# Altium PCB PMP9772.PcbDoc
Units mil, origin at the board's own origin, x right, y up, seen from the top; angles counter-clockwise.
Board outline 3300 x 2400 mil, 2 copper layers (Top Layer, Bottom Layer), stack 64.8 mil thick; 65 components, 20 nets, 122 pads, 261 vias.
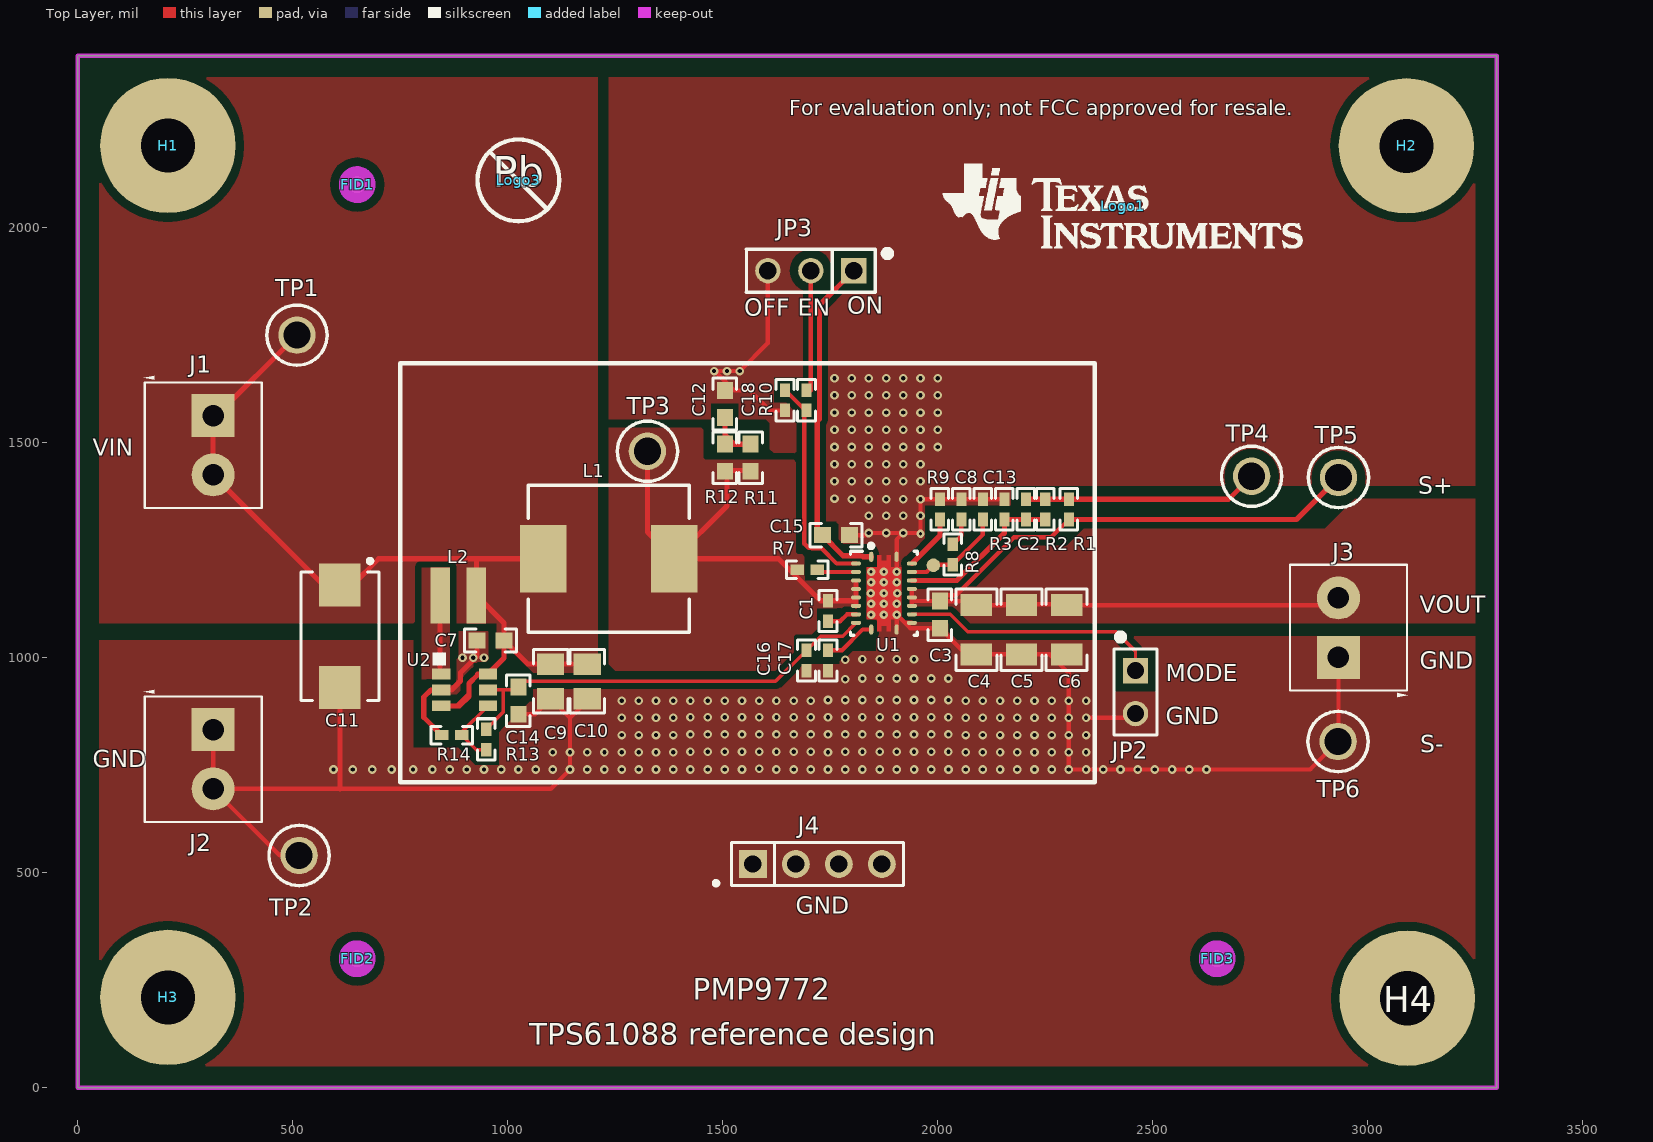
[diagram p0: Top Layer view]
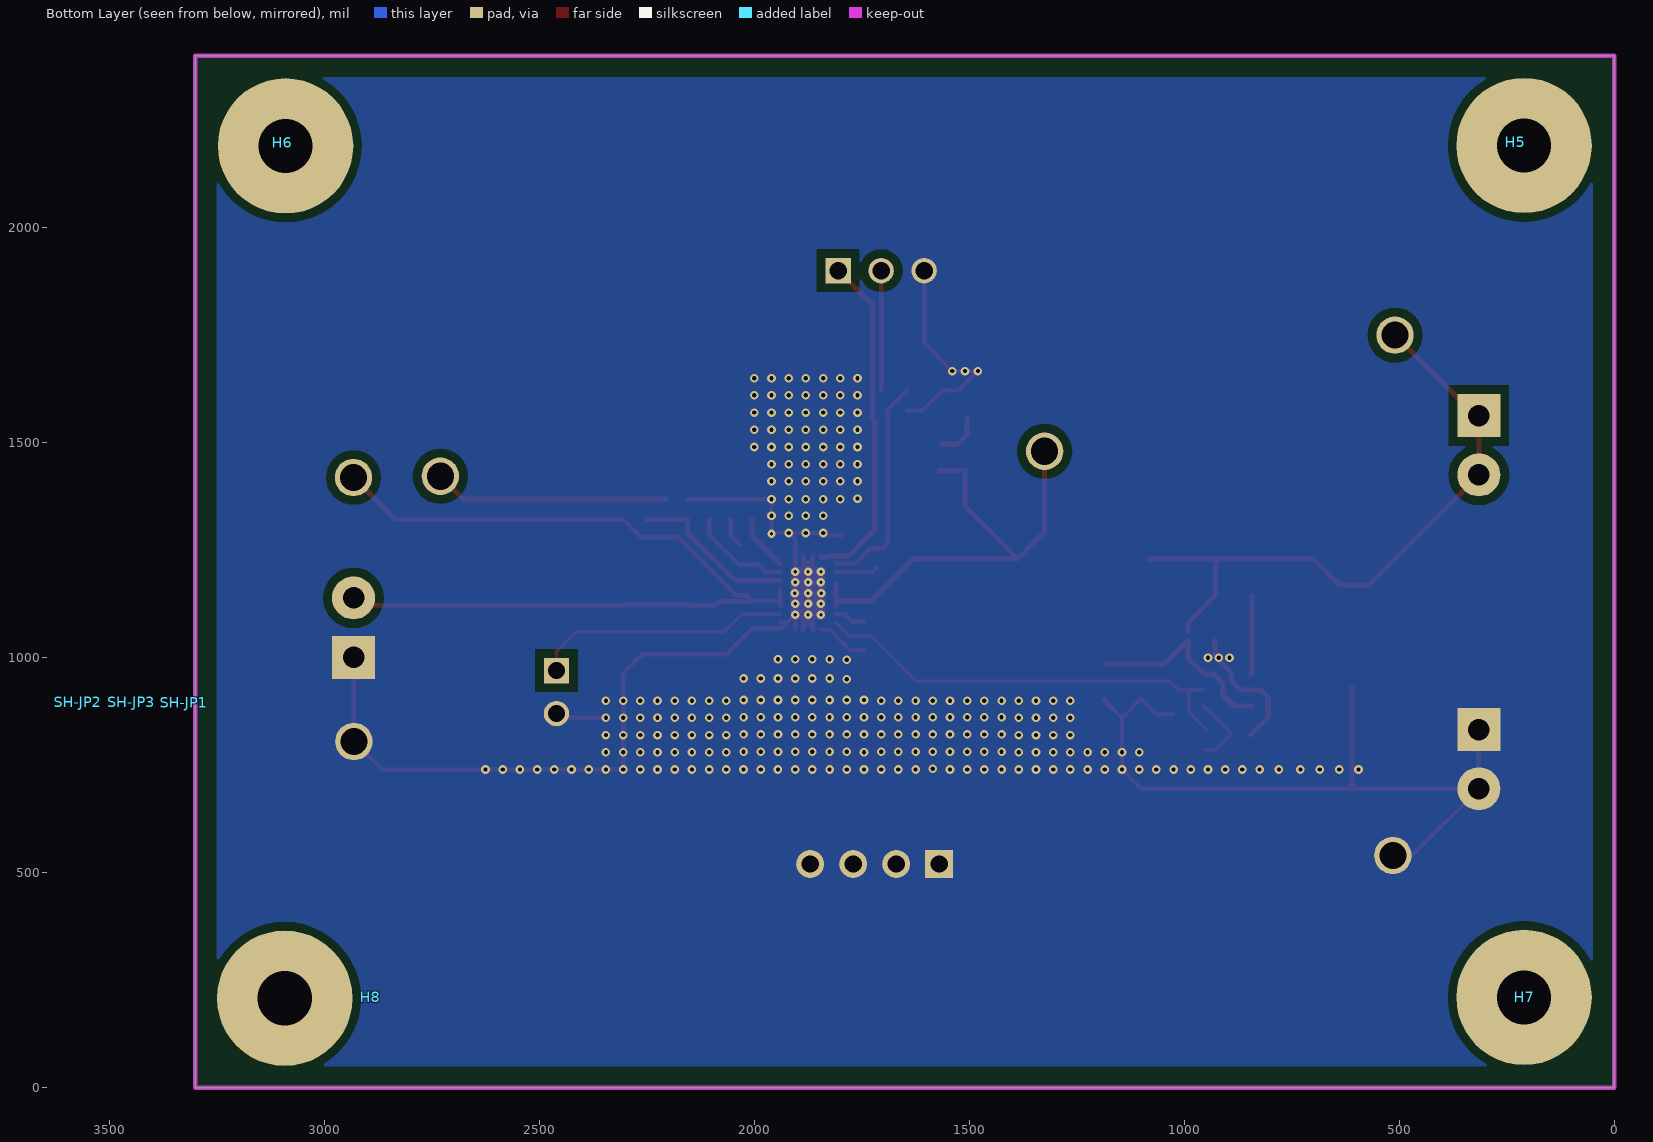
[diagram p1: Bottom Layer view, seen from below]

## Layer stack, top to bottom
Top Solder: solder mask 0.4, Solder Resist, Dk 3.5
Top Layer: signal copper 2.8
Dielectric1: core 59.2, FR-4, Dk 4.8
Bottom Layer: signal copper 2.8
Bottom Solder: solder mask 0.4, Solder Resist, Dk 3.5

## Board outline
0,0 3300,0 3300,2400 0,2400

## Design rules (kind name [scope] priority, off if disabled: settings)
AcuteAngle [All] p1: minimum=4.50000000000000E+0001 checktracksonly=FALSE
AssemblyTestPointUsage [All] p1: valid=2
Clearance Clearance_BoardEdge_MountingHoles [OnCopper and InComponentClass('Mounting Holes') vs IsKeepOut] p1: gap=40
Clearance Clearance_BoardEdge_Poly [OnCopper and InPoly vs IsKeepOut] p2: gap=20
Clearance Clearance_BoardEdge [All vs IsKeepOut] p3 off: gap=75
Clearance Clearance_Poly [InPolygon] p4: gap=20 except(14: SMDPad-Poly Fill-Poly Track-Poly; 16: Poly-Poly)
Clearance [All] p5: gap=7 except(5: THPad-Via Via-Via)
ComponentClearance ComponentClearance_Logo [InComponentClass('Logo')] p1: gap=50 collisioncheckmode=3 verticalgap=10 showdistances=FALSE
ComponentClearance ComponentClearance_ScrewToNut [(HasFootprint('NY PMS 440 0025 PH')) vs (HasFootprint('Keystone_1902C'))] p2 off: gap=0.3 collisioncheckmode=3 verticalgap=0.3 showdistances=FALSE
ComponentClearance ComponentClearance_MountingHoles [InComponentClass('Mounting Holes')] p3 off: gap=250 collisioncheckmode=3 verticalgap=100000 showdistances=FALSE
ComponentClearance ComponentClearance_SmallPassives [HasFootprint('0201*') or HasFootprint('0402*') or HasFootprint('0508') or HasFootprint('0603*') or HasFootprint('0612') or HasFootprint('0805*') or HasFootprint('0815*') or HasFootprint('0830*') or HasFootprint('1206*') or HasFootprint('1210*') or HasFootprint('1808*') or HasFootprint('1812*') or HasFootprint('1825*') or HasFootprint('2010*') or HasFootprint('2220*') or HasFootprint('2225*') or HasFootprint('2512*') or HasFootprint('2728*') or HasFootprint('3518*') vs HasFootprint('0201*') or HasFootprint('0402*') or HasFootprint('0508') or HasFootprint('0603*') or HasFootprint('0612') or HasFootprint('0805*') or HasFootprint('0815*') or HasFootprint('0830*') or HasFootprint('1206*') or HasFootprint('1210*') or HasFootprint('1808*') or HasFootprint('1812*') or HasFootprint('1825*') or HasFootprint('2010*') or HasFootprint('2220*') or HasFootprint('2225*') or HasFootprint('2512*') or HasFootprint('2728*') or HasFootprint('3518*')] p4: gap=5 collisioncheckmode=3 verticalgap=5 showdistances=FALSE
ComponentClearance ComponentClearance_THtoSMT [IsThruComponent vs IsSMTComponent] p5: gap=0 collisioncheckmode=3 verticalgap=0 showdistances=FALSE
ComponentClearance ComponentClearance_THtoTH [IsThruComponent vs IsThruComponent] p6: gap=0 collisioncheckmode=3 verticalgap=0 showdistances=FALSE
ComponentClearance [All] p7: gap=5 collisioncheckmode=3 verticalgap=5 showdistances=FALSE
DiffPairsRouting [All] p1: maxlimit=100 minlimit=10 mostfreqgap=10 toplayer_minwidth=15 toplayer_maxwidth=15 toplayer_prefwidth=15 bottomlayer_minwidth=15 bottomlayer_maxwidth=15 bottomlayer_prefwidth=15 maxuncoupledlength=1000
FabricationTestPointUsage TestPointUsage [All] p1: valid=2 allowmultiple=FALSE
FabricationTestpoint Testpoint [All] p1: side=3 testpointundercomponent=TRUE minsize=40 maxsize=100 preferedsize=60 minholesize=0 maxholesize=40 preferedholesize=32 testpointgrid=1 allowsidetop=TRUE allowsidebottom=TRUE usegrid=TRUE gridtolerance=0.01
FanoutControl Fanout_LCC [IsLCC] p1: bgadir=Out bgaviamode=Centered fanoutstyle=Auto fanoutdirection=Alternating viagrid=1 // Fanout_LCC (Default Rule)
FanoutControl Fanout_BGA [IsBGA] p2: bgadir=Out bgaviamode=Centered fanoutstyle=Auto fanoutdirection=Alternating viagrid=1 // Fanout_BGA (Default Rule)
FanoutControl Fanout_Default [All] p4: bgadir=Out bgaviamode=Centered fanoutstyle=Auto fanoutdirection=Alternating viagrid=1 // Fanout_Default (Default Rule)
FanoutControl Fanout_Small [(CompPinCount < 5)] p5: bgadir=Out bgaviamode=Centered fanoutstyle=Auto fanoutdirection=OutThenIn viagrid=1 // Fanout_Small (Default Rule)
HoleSize [All] p1: absolutevalues=TRUE maxlimit=251 minlimit=8 maxpercent=80.000 minpercent=20.000
MinimumAnnularRing MinimumAnnularRing_ThermalPadVias [IsVia and InAnyComponent] p1: minimumring=5.91
MinimumAnnularRing [All] p2: minimumring=9
MinimumSolderMaskSliver MinimumSolderMaskSliver_Logo [InComponentClass('Logo') vs InComponentClass('Logo')] p1: minsoldermaskwidth=0.7
MinimumSolderMaskSliver [All] p2: minsoldermaskwidth=3.94
PlaneConnect [All] p1: planeconnectstyle=Direct reliefexpansion=10 reliefentries=4 reliefconductorwidth=10 reliefairgap=10
PolygonConnect PolygonConnect_5 [All vs IsNamedPolygon('Top Layer-No Net')] p1: connectstyle=Direct reliefconductorwidth=10 reliefentries=4 polygonreliefangle="90 Angle" airgapwidth=10
PolygonConnect PolygonConnect_4 [All] p2: connectstyle=Direct reliefconductorwidth=10 reliefentries=4 polygonreliefangle="90 Angle" airgapwidth=10
PolygonConnect PolygonConnect_3 [All vs IsNamedPolygon('Top Layer-No Net')] p3: connectstyle=Direct reliefconductorwidth=10 reliefentries=4 polygonreliefangle="90 Angle" airgapwidth=10
PolygonConnect PolygonConnect_2 [All vs IsNamedPolygon('Bottom Layer-No Net')] p4: connectstyle=Direct reliefconductorwidth=10 reliefentries=4 polygonreliefangle="90 Angle" airgapwidth=10
PolygonConnect PolygonConnect_1 [All vs IsNamedPolygon('Bottom Layer-No Net')] p5: connectstyle=Direct reliefconductorwidth=10 reliefentries=4 polygonreliefangle="90 Angle" airgapwidth=10
PolygonConnect [IsVia + IsNamedPolygon(PGND) + InNamedPolygon(VIN)] p6: connectstyle=Relief reliefconductorwidth=10 reliefentries=4 polygonreliefangle="90 Angle" airgapwidth=10
RoutingVias ThermalPadVias [IsVia and InAnyComponent] p1: holewidth=7.87 width=19.68 viastyle="Through Hole" minholewidth=7.87 minwidth=19.68 maxholewidth=12.99 maxwidth=23.62
RoutingVias [All] p2: holewidth=16 width=34 viastyle="Through Hole" minholewidth=7.87 minwidth=26 maxholewidth=40 maxwidth=65
SMDToCorner [All] p1: distance=30000
SilkToSilkClearance [All] p1: silktosilkclearance=5
SilkToSolderMaskClearance SilkscreenOverComponentPads [IsPad] p1: minsilkscreentomaskgap=5 clearancetoexposedcopper=TRUE
SolderMaskExpansion [All] p1: expansion=1.97
UnpouredPolygon [All] p1: allowunpoured=FALSE
Width [All] p1: maxlimit=100 minlimit=6 preferedwidth=10 checkconnectedcopper=TRUE
15 further rules are at their usual default settings.

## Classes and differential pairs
component class AssemblyNote: ZZ1 ZZ2 ZZ3
component class PMP9772: C1 C2 C3 C4 C5 C6 C7 C8 C9 C10 C11 C12 C13 C14 C15 C16 C17 C18 J1 J2 J3 J4 JP2 JP3 L1 L2 R1 R2 R3 R4 R7 R8 R9 R10 R11 R12 R13 R14 TP1 TP2 TP3 TP4 TP5 TP6 U1 U2
component class Shunt: SH-JP1 SH-JP2 SH-JP3
component class Header: J4 JP2
component class "Mounting Holes": H1 H2 H3 H4
component class Logo: Logo1
component class PMP9772_Hardware: FID1 FID2 FID3 H1 H2 H3 H4 H5 H6 H7 H8 H9 Logo1 Logo2 Logo3 SH-JP1 SH-JP2 SH-JP3 ZZ1 ZZ2 ZZ3
component class FiducialMark: FID1 FID2 FID3

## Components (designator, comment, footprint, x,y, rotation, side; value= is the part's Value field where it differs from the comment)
C1 "GRM155R61C104KA88D" 0402 1745,1108.62 r270 top
C2 "C1005C0G1E102J" 0402 2205,1345 r270 top
C3 "GRM188R71E105KA12D" 0603 2005,1100 r270 top
C4 "GRM31CR61C226KE15L" 1206 2090,1065 r270 top
C5 "GRM31CR61C226KE15L" 1206 2195,1065 r270 top
C6 "GRM31CR61C226KE15L" 1206 2300,1065 r270 top
C7 "0603ZD475KAT2A" 0603 960,1040 r0 top
C8 "GRM155R71C103KA01D" 0402 2055,1345 r90 top
C9 "C2012X5R0J226M" 0805_HV 1100,945 r270 top
C10 "C2012X5R0J226M" 0805_HV 1185,945 r270 top
C11 "T495V157M010ATE150" 7343-20 610,1050 r270 top
C12 "GRM188R72A102KA01D" 0603 1505,1590 r90 top
C13 "GRM1555C1H470FA01D" 0402 2105,1345 r90 top
C14 "0603ZD475KAT2A" 0603 1025,900 r90 top
C15 "0603ZD475KAT2A" 0603 1763.5,1285 r180 top
C16 "GRM155R61C104KA88D" 0402 1695,993.62 r270 top
C17 "GRM155R71C473KA01D" 0402 1745,993.62 r90 top
C18 "GRM155R61C104KA88D" 0402 1645,1598.62 r270 top
FID1 "Fiducial" Fiducial10-20#1 650,2000 r0 top locked
FID2 "Fiducial" Fiducial10-20#2 650,300 r0 top locked
FID3 "Fiducial" Fiducial10-20#2 2650,300 r0 top locked
H1 "NY PMS 440 0025 PH" "NY PMS 440 0025 PH"#1 230,2199 r0 top
H2 "NY PMS 440 0025 PH" "NY PMS 440 0025 PH"#2 3098,2198 r0 top
H3 "NY PMS 440 0025 PH" "NY PMS 440 0025 PH"#3 210,210 r0 top locked
H4 "NY PMS 440 0025 PH" "NY PMS 440 0025 PH"#3 3092,208 r0 top
H5 "1902C" Keystone_1902C#1 230,2199 r180 bottom locked
H6 "1902C" Keystone_1902C#1 3098,2198 r180 bottom locked
H7 "1902C" Keystone_1902C#1 210,210 r180 bottom locked
H8 "1902C" Keystone_1902C#2 2893,210 r180 bottom
J1 "ED555/2DS" TERM_BLK_ED555-2DS 315,1563 r270 top
J2 "ED555/2DS" TERM_BLK_ED555-2DS 315,833 r270 top
J3 "ED555/2DS" TERM_BLK_ED555-2DS 2932,1001 r90 top
J4 "TSW-104-07-G-S" TSW-104-07-G-S 1720,520 r0 top
JP2 "PEC02SAAN" CONN_PEC02SAAN 2460,920 r270 top
JP3 "PEC03SAAN" CONN_PEC03SAAN 1705,1900 r180 top
L1 "CDMC8D28NP-R68MC" CDMC8D28 1235,1230 r0 top
L2 "LQH3NPN6R8NG0" LQH3NP_G0 885,1145 r180 top
Logo1 "Texas Instruments" TI_Stacked_Overlay_Small 2430,2050 r0 top
Logo2 "FCC disclaimer" FCC_disclaimer 3827,3801 r90 top
Logo3 "Pb-Free Symbol" Pb-Free_Overlay_Medium 1025,2110 r0 top
R1 "CRCW040249R9FKED" 0402 2305,1345 r270 top
R2 "CRCW0402205KFKED" 0402 2250,1345 r270 top
R3 "CRCW0402120KFKED" 0402 2155,1345 r270 top
R7 "CRCW0402255KFKED" 0402 1696.77,1204.61 r180 top
R8 "CRCW04024K99FKED" 0402 2035,1240 r270 top
R9 "CRCW0402100KFKED" 0402 2005,1345 r270 top
R10 "RC0402JR-070RL" 0402 1695,1598.62 r90 top
R11 "CRCW06032R05FKEA" 0603 1565,1465 r90 top
R12 "CRCW06032R05FKEA" 0603 1505,1465 r90 top
R13 "CRCW04021M00FKED" 0402 950,810 r90 top
R14 "CRCW0402162KFKED" 0402 870,820 r0 top
SH-JP1 "969102-0000-DA" SNT-100-BK-G 3327,895 r90 bottom
SH-JP2 "969102-0000-DA" SNT-100-BK-G 3573,896 r90 bottom
SH-JP3 "969102-0000-DA" SNT-100-BK-G 3449,896 r90 bottom
TP1 "5010" Keystone5010 510,1750 r0 top
TP2 "5010" Keystone5010 515,540 r0 top
TP3 "5010" Keystone5010 1325,1480 r90 top
TP4 "5010" Keystone5010 2730,1422 r90 top
TP5 "5010" Keystone5010 2932,1419 r0 top
TP6 "5010" Keystone5010 2931,805 r0 top
U1 "TPS61088RHLR" RHL0020A 1875,1150 r0 top locked (schematic designator U?)
U2 "TLV61220DBV" DBV-6 900,925 r0 top
ZZ1 "These assemblies are ESD sensitive, ESD precautions shall be observed." AssemblyNote 4050,3305 r90 top
ZZ2 "These assemblies must be clean and free from flux and all contaminants. Use of no clean flux is not acceptable." AssemblyNote 4045,2895 r90 top
ZZ3 "These assemblies must comply with workmanship standards IPC-A-610 Class 2, unless otherwise specified." AssemblyNote 4050,2475 r90 top

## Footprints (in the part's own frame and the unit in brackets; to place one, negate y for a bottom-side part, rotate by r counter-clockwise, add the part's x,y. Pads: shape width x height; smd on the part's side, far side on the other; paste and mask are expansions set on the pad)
0402 [mm] "0402 from SM-752 data"
  rect 0.8x0.6 smd: 1(-0.6,0) 2(0.6,0)
  silkscreen extent -1.22,-0.52 1.22,0.52, body extent -0.55,-0.3 0.55,0.3, height 0.6
0603 [mm] "0603 from SM-752 data"
  rect 1x0.95 smd: 1(-0.8,0) 2(0.8,0)
  silkscreen extent -1.52,-0.69 1.52,0.69, body extent -0.87,-0.47 0.87,0.47, height 0.85
0805_HV [mil] "0805 with 30mil clearance between pads"
  rect 50x63 smd: 1(-40,0) 2(40,0)
  silkscreen extent -74,-40 74,40, body extent -43,-29 43,29, height 43
1206 [mm] "1206 from SM-752 data"
  rect 1.3x1.85 smd: 1(-1.45,0) 2(1.45,0)
  silkscreen extent -2.4,-1.21 2.4,1.21, body extent -1.7,-0.9 1.7,0.9, height 1.35
7343-20 [mm] "Medium density IPC, based on Kemet case V from T495 datasheet"
  rect 2.55x2.45 smd: 1(-3.025,0) 2(3.025,0)
  silkscreen extent -4.56,-2.3 3.8,2.3, body extent -3.8,-2.3 3.8,2.3, height 2
AssemblyNote [mil] "Assembly Note"
CDMC8D28 [mm] "SMD, 2-Leads, Body 9.5x8.7mm"
  rect 2.75x4 smd: 1(-3.875,0) 2(3.875,0)
  silkscreen extent -4.75,-4.35 4.75,4.35, body extent -4.75,-4.35 4.75,4.35, height 3
CONN_PEC02SAAN [mm] "SULLINS"
  rect 1.5x1.5 hole 1.016: 1(-1.27,0)
  round 1.5 hole 1.016: 2(1.27,0)
  silkscreen extent -3.45,-1.27 2.54,1.27, body extent -2.54,-1.27 2.54,1.27, height 8.38
CONN_PEC03SAAN [mm] "SULLINS"
  rect 1.5x1.5 hole 1.016: 1(-2.54,0)
  round 1.5 hole 1.016: 2(0,0) 3(2.54,0)
  silkscreen extent -4.72,-1.27 3.81,1.27, body extent -3.84,-1.3 3.84,1.3, height 8.38
DBV-6 [mil]
  rect 42x25 smd: 1(-54.5,37) 2(-54.5,0) 3(-54.5,-37) 4(54.5,-37) 5(54.5,0) 6(54.5,37)
  silkscreen extent -75,57 -44,87
FCC_disclaimer [mil]
Fiducial10-20#1 [mm]
  round 1 smd paste-0.5 mask+0.5: 1(0,2.54)
  Top Layer keep-out circle w1.178: c0,2.54 r0.5
Fiducial10-20#2 [mm]
  round 1 smd paste-0.5 mask+0.5: 1(0,0)
  Top Layer keep-out circle w1.178: c0,0 r0.5
Keystone5010 [mil] "Keystone Multipurpose loops"
  round 87 hole 63: 1(0,0)
  silkscreen extent -70,-70 70,70, body extent -63,-63 63,62, height 319
Keystone_1902C#1 [mil] "Hex Standoff, 4-40 threaded, nylon"
  body extent -145,-126 146,126, height 501
Keystone_1902C#2 [mil] "Hex Standoff, 4-40 threaded, nylon"
  round 1 on Mech4: 0(0,0)
  body extent -145,-126 146,126, height 501
LQH3NP_G0 [mm] "MURATA"
  rect 1.15x3.3 smd: 1(-1.075,0) 2(1.075,0)
  body extent -1.6,-1.6 1.6,1.6, height 1.01
"NY PMS 440 0025 PH"#1 [mm] "4-40 nylon screw and mounting hole"
  round 8 hole 3.2: 1(-0.508,-0.203)
  body extent -3.3,-3.3 3.3,3.3, height 2.69
"NY PMS 440 0025 PH"#2 [mm] "4-40 nylon screw and mounting hole"
  round 8 hole 3.2: 1(-0.203,-0.203)
  body extent -3.3,-3.3 3.3,3.3, height 2.69
"NY PMS 440 0025 PH"#3 [mm] "4-40 nylon screw and mounting hole"
  round 8 hole 3.2: 1(0,0)
  body extent -3.3,-3.3 3.3,3.3, height 2.69
Pb-Free_Overlay_Medium [mil]
  silkscreen extent -95,-95 95,95
RHL0020A [mm] "QFN, 20-Leads, Body 4.5x3.5mm, Pitch 0.5mm, Thermal Pad 3.05x2.05mm, TI Recommended"
  oval 0.24x0.6 smd: 1(-0.75,2.15) 10(-0.75,-2.15) 11(0.75,-2.15) 20(0.75,2.15)
  oval 0.6x0.24 smd: 2(-1.65,1.75) 3(-1.65,1.25) 4(-1.65,0.75) 5(-1.65,0.25) 6(-1.65,-0.25) 7(-1.65,-0.75) 8(-1.65,-1.25) 9(-1.65,-1.75) 12(1.65,-1.75) 13(1.65,-1.25) 14(1.65,-0.75) 15(1.65,-0.25) 16(1.65,0.25) 17(1.65,0.75) 18(1.65,1.25) 19(1.65,1.75)
  rect 0.3x0.3 smd paste-0.15 mask+0: 21(0,0)
  Top Layer region: 0.16,2.25 0.16,1.925 -0.16,1.925 -0.16,2.25 -0.39,2.25 -0.39,1.525 -1.025,1.525 -1.025,-1.525 -0.39,-1.525 -0.39,-2.25 -0.16,-2.25 -0.16,-1.925 0.16,-1.925 0.16,-2.25 0.39,-2.25 0.39,-1.525 1.025,-1.525 1.025,1.525 0.39,1.525 0.39,2.25
  silkscreen extent -1.98,-2.47 1.98,2.47, body extent -1.82,-2.33 1.83,2.32, height 1.01
SNT-100-BK-G [mil] "Samtec STEP model"
  round 1 on Mech4: 0(0,0)
  body extent -100,-50 100,50, height 344
TERM_BLK_ED555-2DS [mil]
  rect 100x100 hole 50: 1(0,0)
  round 100 hole 50: 2(138,0)
  silkscreen extent -93,-161 215,113, body extent -69,-150 207,106, height 323
TI_Stacked_Overlay_Small [mil]
  silkscreen extent -418,-98 418,98
TSW-104-07-G-S [mm] "Samtec 100mil, 1x4, 230 mil above insulator"
  rect 1.65x1.65 hole 1.016 mask+0: 1(-3.81,0)
  round 1.65 hole 1.016 mask+0: 2(-1.27,0) 3(1.27,0) 4(3.81,0)
  silkscreen extent -6.1,-1.27 5.08,1.27, body extent -5.08,-1.27 5.08,1.27, height 8.38

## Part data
C1 C16 C18: "CAP, CERM, 0.1uF, 16V, +/-10%, X5R, 0402"
C2: "CAP, CERM, 1000pF, 25V, +/-5%, C0G/NP0, 0402"
C3: "CAP, CERM, 1 μF, 25 V, +/- 10%, X7R, 0603"
C4 C5 C6: "CAP, CERM, 22 μF, 16 V, +/- 10%, X5R, 1206"
C7 C14 C15: "CAP, CERM, 4.7uF, 10V, +/-10%, X5R, 0603"
C8: "CAP, CERM, 0.01 μF, 16 V, +/- 10%, X7R, 0402"
C9 C10: "CAP, CERM, 22 μF, 6.3 V, +/- 20%, X5R, 0805"
C11: "CAP, TA, 150 μF, 10 V, +/- 20%, 0.15 ohm, SMD"
C12: "CAP, CERM, 1000 pF, 100 V, +/- 10%, X7R, 0603"
C13: "CAP, CERM, 47 pF, 50 V, +/- 1%, C0G, 0402"
C17: "CAP, CERM, 0.047 μF, 16 V, +/- 10%, X7R, 0402"
FID1 FID2 FID3: "Fiducial mark.  There is nothing to buy or mount."
H1 H2 H3 H4: "Machine Screw, Round, #4-40 x 1/4, Nylon, Philips panhead"
H5 H6 H7 H8: "Standoff, Hex, 0.5\"L #4-40 Nylon"
J1 J2 J3: "Terminal Block, 6A, 3.5mm Pitch, 2-Pos, TH"
J4: "Header, 100mil, 4x1, Gold, TH"
JP2: "Header, 100mil, 2x1, Tin, TH"
JP3: "Header, 100mil, 3x1, Tin plated, TH"
L1: "Inductor, Shielded Drum Core, Metal Composite, 680 nH, 15.4 A, 0.00384 ohm, SMD"
L2: "Inductor, Wirewound, Ferrite, 6.8 μH, 0.65 A, 0.45 ohm, SMD"
Logo1: library part TI_Logo, "Texas Instrument Corporate Signature"
Logo2: library part FCC_disclaimer, "FCC_disclaimer"
Logo3: library part Pb-Free
R1: "RES, 49.9 ohm, 1%, 0.063W, 0402"
R2: "RES, 205 k, 1%, 0.063 W, 0402"
R3: "RES, 120 k, 1%, 0.063 W, 0402"
R7: "RES, 255 k, 1%, 0.063 W, 0402"
R8: "RES, 4.99 k, 1%, 0.063 W, 0402"
R9: "RES, 100k ohm, 1%, 0.063W, 0402"
R10: "RES, 0 ohm, 5%, 0.063W, 0402"
R11 R12: "RES, 2.05, 1%, 0.1 W, 0603"
R13: "RES, 1.00 M, 1%, 0.063 W, 0402"
R14: "RES, 162 k, 1%, 0.063 W, 0402"
SH-JP1 SH-JP2 SH-JP3: "Shunt, 100mil, Gold plated, Black"
TP1 TP2 TP3 TP4 TP5 TP6: "Test Point, TH, Multipurpose, Red"
U1: "13.2-V Output, Synchronous Boost Converter with 10-A Switch, RHL0020A"
U2: "IC, High Efficient, Tiny 1Cell LiIon or 1-3 Cells Alk/Nixx Boost Converter"
ZZ1 ZZ2 ZZ3: library part AssemblyNote

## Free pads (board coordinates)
  round 31.5 smd: 0(1990,1215)

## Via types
v1: diameter 20, hole 10, Top Layer to Bottom Layer, tented both sides, 229 vias
v2: diameter 20, hole 10, Top Layer to Bottom Layer, tented bottom, 16 vias
v3: diameter 19.68, hole 7.87, Top Layer to Bottom Layer, 11 vias
v4: diameter 19.68, hole 7.87, Top Layer to Bottom Layer, tented bottom, 4 vias
v5: diameter 19.68, hole 7.87, Top Layer to Bottom Layer, tented both sides, 1 vias

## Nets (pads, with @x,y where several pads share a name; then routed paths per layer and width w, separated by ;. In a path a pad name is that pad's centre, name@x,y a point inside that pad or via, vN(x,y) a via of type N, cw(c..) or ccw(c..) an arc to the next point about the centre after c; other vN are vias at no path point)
MODE: JP2.1 U1.13 | length 600.6
  Top Layer w8: U1.13 2029.21,1100.79 2070,1060 2350,1060 2415,1060 2460,1015 JP2.1
NetC1_2: C1.2 U1.8 | length 71.6
  Top Layer w10: C1.2 1773.41,1085 1789.2,1100.79 U1.8
NetC2_1: C2.1 R1.1 R2.1 TP4.1 | length 547.1
  Top Layer w12: C2.1 R2.1 R1.1 2676.62,1368.62 TP4.1
NetC2_2: C2.2 R2.2 R3.2 U1.17 | length 387.2
  Top Layer w12: U1.17 2044.53,1179.53 2155,1290 R3.2 C2.2 R2.2
NetC8_1: C8.1 R8.1 | length 66
  Top Layer w10: R8.1 2055,1283.62 C8.1
NetC12_1: C12.1 R11.2 R12.2 | length 157
  Top Layer w12: C12.1 1505,1519.18 ; 1543.3,1496.5 1527.69,1496.5 ; R11.2 1527.69,1496.5 ; 1505,1519.18 1505,1518.2 1526.7,1496.5 1527.69,1496.5 ; 1505,1519.18 1527.69,1496.5
NetC13_1: C13.1 pad.0 R8.2 U1.18 | length 236.1
  Top Layer w10: U1.18 1974.21,1199.21 pad.0 1991.38,1216.38 R8.2 2105,1286.38 C13.1
NetC17_2: C17.2 U1.10 | length 120.4
  Top Layer w10: C17.2 1777.24,1017.24 1825.36,1065.36 U1.10
NetC18_1: C18.1 R10.1 U1.2 | length 516.9
  Top Layer w10: C18.1 1692.24,1575 1690,1572.76 1690,1265 1700,1255 1706.65,1255 1707.35,1254.3 1729.5,1254.3 1764.91,1218.9 U1.2
NetJP3_2: JP3.2 R10.2 | length 278.5
  Top Layer w10: R10.2@1705,1621.5 JP3.2
NetL2_2: L2.2 U2.1 | length 184.2
  Top Layer w12: L2.2 842.68,964.82 U2.1
NetR7_1: R7.1 U1.3 | length 99.5
  Top Layer w10: R7.1@1715,1210 1725.79,1199.21 U1.3
NetR9_2: R9.2 U1.19 | length 129.4
  Top Layer w12: U1.19 2005,1283.94 R9.2
NetR13_1: R13.1 R14.2 U2.4 | length 163.5
  Top Layer w8: R13.1 927.24,786.38 R14.2 893.62,827.12 U2.4
PGND: C3.2 C4.2 C5.2 C6.2 C7.1 C8.2 C9.2 C10.2 C11.2 C12.2 C13.2 C14.1 C15.1 C16.2 C17.1 C18.2 J2.1 J2.2 J3.1 J4.1 J4.2 J4.3 J4.4 JP2.2 JP3.3 R3.1 R9.1 R14.1 TP2.1 TP6.1 U1.11 U1.12 U1.20 U1.21 U2.2 | length 4918.8
  Top Layer w10: J2.1 J2.2 ; TP2.1 470,540 J2.2 ; C14.1 1063.5,868.5 C9.2 1145,860 ; C10.2 1185,900 1145,860 ; v1(1480,1666.5) v1@1481.7,1666.5 ; JP3.3 1605,1731.5 v1(1540,1666.5) v1(1510,1666.5) v1@1481.7,1666.5 ; C18.2 1610,1575 1563.5,1621.5 1526.7,1621.5 v1@1481.7,1666.5 ; C15.1 1835,1285 v1(1840,1290) v1(1880,1290) v1(1920,1290) ; U1.11 1905,1065.83 v3(1905,1100) 1923.9,1081.1 ; v3(1905,1200) 1905,1234.18 U1.20 1904.53,1274.53 v1(1920,1290) ; U1.12 1923.9,1081.1 ; v5@1958.52,1290 v1(1920,1290) ; v5(1960.03,1288.49) v1(1960.03,1368.49) ; v1@1960.03,1370.03 v1(1960.03,1368.49) ; 2019.81,1368.49 2069.68,1368.49 2069.81,1368.62 C13.2 R3.1 ; 2040.19,1368.62 R9.1 2004.86,1368.49 v1(1960.03,1368.49) ; v1(2345,860) 2450,860 JP2.2 ; J3.1 2932,806 TP6.1 2866,740 v1(2625,740) v1(2585,740) v1(2545,740) v1(2505,740) v1(2465,740) v1(2425,740) v1(2385,740) v1(2345,740) v1(2305,740) v1(2305,780) v1(2305,820) 2305,963.5 2260.58,1007.91 C5.2 C4.2 2065.59,1007.91 C3.2 1936.5,1068.5 1923.9,1081.1 ; J2.2 610,695 1100,695 v1(1145,740) 1145,860
  Top Layer w12: 610,695 C11.2 ; R14.1 805,861.38 805,908.5 821.5,925 U2.2 869.5,925 890,945.5 890,965 928.5,1003.5 C7.1
  other v1: 595,740 640,740 685,740 730,740 780,740 825,740 865,740 905,740 945,740 985,740 1025,740 1065,740 1105,740 1185,740 1225,740 1305,740 1345,740 1385,740 1425,740 1465,740 1505,740 1545,740 1625,740 1665,740 1705,740 1745,740 1785,740 1825,740 1865,740 1905,740 1945,740 1985,740 2025,740 2065,740 2105,740 2145,740 2185,740 2225,740 2265,740 1584.97,741.51 1105,780 1145,780 1185,780 1225,780 1305,780 1345,780 1385,780 1745,780 2065,780 2105,780 2145,780 2185,780 2225,780 2265,780 2345,780 1424.97,781.51 1464.97,781.51 1504.97,781.51 1544.97,781.51 1584.97,781.51 1624.97,781.51 1664.97,781.51 1704.97,781.51 1784.97,781.51 1824.97,781.51 1864.97,781.51 1904.97,781.51 1944.97,781.51 1984.97,781.51 2024.97,781.51 1305,820 1345,820 1385,820 2065,820 2105,820 2145,820 2185,820 2225,820 2265,820 2345,820 1424.97,821.51 1464.97,821.51 1504.97,821.51 1544.97,821.51 1584.97,821.51 1624.97,821.51 1664.97,821.51 1704.97,821.51 1744.97,821.51 1784.97,821.51 1824.97,821.51 1864.97,821.51 1904.97,821.51 1944.97,821.51 1984.97,821.51 2024.97,821.51 1305,860 1345,860 1385,860 2065,860 2105,860 2145,860 2185,860 2225,860 2265,860 2305,860 1424.97,861.51 1464.97,861.51 1504.97,861.51 1544.97,861.51 1584.97,861.51 1624.97,861.51 1664.97,861.51 1704.97,861.51 1744.97,861.51 1784.97,861.51 1824.97,861.51 1864.97,861.51 1904.97,861.51 1944.97,861.51 1984.97,861.51 2024.97,861.51 1305,900 1345,900 1385,900 1425,900 1465,900 1505,900 1545,900 1585,900 1625,900 1665,900 1705,900 2065,900 2105,900 2145,900 2185,900 2225,900 2265,900 2305,900 2345,900 1744.97,901.51 1784.97,901.51 1824.97,901.51 1864.97,901.51 1904.97,901.51 1944.97,901.51 1984.97,901.51 2024.97,901.51 1944.97,996.51 895,1000 920,1000 945,1000 1840,1330 1880,1330 1920,1330 1960,1330 1800.03,1368.49 1840.03,1368.49 1880.03,1368.49 1920.03,1368.49 1760,1370 1760,1410 1800,1410 1840,1410 1880,1410 1920,1410 1960,1410 1760,1450 1800,1450 1840,1450 1880,1450 1920,1450 1960,1450 1760,1490 1800,1490 1840,1490 1880,1490 1920,1490 1960,1490 2000,1490 1760,1530 1800,1530 1840,1530 1880,1530 1920,1530 1960,1530 2000,1530 1760,1570 1800,1570 1840,1570 1880,1570 1920,1570 1960,1570 2000,1570 1760,1610 1800,1610 1840,1610 1880,1610 1920,1610 1960,1610 2000,1610 1760,1650 1800,1650 1840,1650 1880,1650 1920,1650 1960,1650 2000,1650
  other v2: 1265,740 1265,780 1265,820 1265,860 1265,900 1785,950 1824.97,951.51 1864.97,951.51 1904.97,951.51 1944.97,951.51 1984.97,951.51 2024.97,951.51 1785,995 1824.97,996.51 1864.97,996.51 1904.97,996.51
  other v3: 1845,1100 1845,1125 1875,1125 1905,1125 1875,1150 1845,1175 1875,1175 1905,1175 1845,1200
  other v4: 1875,1099.81 1844.48,1150 1905.51,1150 1875,1200.2
SW: C1.1 L1.2 R7.2 R11.1 R12.1 TP3.1 U1.4 U1.5 U1.6 U1.7 | length 1108.8
  Top Layer w12: TP3.1 1325,1292.56 L1.2 ; R11.1@1570,1435 1510,1435 1510,1352.44 L1.2 ; U1.7 U1.6 ; 1810.04,1171.41 U1.5 U1.6 ; L1.2 1630,1230 1655,1205 1727.76,1132.24 C1.1 1802.12,1132.24 U1.6
VCC: C15.2 JP3.1 U1.1 | length 789.5
  Top Layer w12: JP3.1 1725,1820 1725,1555 1720,1550 1720,1297.01 C15.2 1780.11,1236.9 1817.49,1236.9 1817.77,1236.62 1824.46,1236.62 1826.44,1234.65 U1.1
VIN: C7.2 C9.1 C10.1 C11.1 J1.1 J1.2 L1.1 L2.1 TP1.1 U2.3 U2.6 | length 2011
  Top Layer w12: TP1.1 323,1563 J1.1 J1.2 570.91,1169.09 C11.1 639.09,1169.09 700,1230 930,1230 ; U2.3 883,888 ; 991.5,1061.7 991.5,1080.83 L2.1 927.32,1227.32 930,1230 ; L1.1 930,1230 ; C10.1 C9.1 1046.5,985 C7.2 991.5,999 U2.6 930.5,962 930.5,960.5 910,940 910,915 ; 883,888 888,888 910,910 910,915 ; 883,888 910,915
VINS: C14.2 C16.1 R13.2 U1.9 U2.5 | length 1028.1
  Top Layer w8: R13.2 990,873.62 990,925 ; U2.5 990,925 ; U1.9 1778.93,1050 1727.76,1050 C16.1 1622.76,945 1033.5,945 1013.5,925 990,925
VO: C3.1 C4.1 C5.1 C6.1 J3.2 R1.2 TP5.1 U1.14 U1.15 U1.16 | length 2100.5
  Top Layer w10: U1.14 1939.96,1132.04 ; U1.16 U1.15 1939.96,1132.04 ; 2147.36,1124.06 2153.61,1124.06 ; R1.2 2263.62,1280 2177.36,1280 2042.36,1145 2018.5,1145 C3.1 ; J3.2 2915.09,1122.09 C6.1 2298.03,1124.06 2153.61,1124.06 ; 1939.96,1132.04 2004.45,1132.04 C3.1 ; C3.1 2080.59,1131.5 C4.1 2155.58,1122.09 2153.61,1124.06
  Top Layer w12: R1.2 2834.38,1321.38 TP5.1
pads on no net: FID1.1 FID2.1 FID3.1 H1.1 H2.1 H3.1 H4.1 H8.0 SH-JP1.0 SH-JP2.0 SH-JP3.0

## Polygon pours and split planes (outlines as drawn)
NetL2_2 on Top Layer "Top Layer-No Net" (solid, remove dead copper, pour order 2): 800,1210 865,1210 865,1080 865,950 800,950 800,1210
VIN on Top Layer "Top Layer-No Net 1" (solid, remove dead copper, pour order 4): 50,2350 600,2350 1150,2350 1210,2350 1210,1080 565,1080 50,1080
SW on Top Layer "Top Layer-No Net 2" (solid, remove dead copper, pour order 6): 1235,1535 1400,1535 1445,1535 1450,1535 1455,1530 1455,1465 1460,1460 1590,1460 1665,1460 1670,1455 1670,1245 1675,1240 1685,1240 1690,1235 1690,1190 1695,1185 1820,1185 1820,1115 1765,1115 1760,1110 1730,1110 1725,1110 1720,1105 1720,1060 1715,1055 1670,1055 1665,1050 1665,1010 1660,1005 1625,970 1500,970 1250,970 1240,980 1235,985 1235,1030
PGND on Top Layer "Top Layer-No Net 3" (solid, remove dead copper, pour order 8): 1235,1555 1350,1555 1600,1555 1610,1545 1610,1485 1620,1475 1980,1475 1990,1465 1990,1355 2170,1355 2170,1400 2500,1400 2600,1400 3250,1400 3250,1650 3250,2350 2450,2350 1235,2350
PGND on Top Layer "Top Layer-No Net 4" (solid, remove dead copper, pour order 10): 1835,1180 1835,1209.69 1834.65,1210.04 1859.65,1210.04 1859.65,1250.35 1859.65,1255.37 1855.37,1259.8 1850,1260 1847.93,1265 1770,1265 1770,1310 1765,1315 1745,1315 1740,1315 1740,1500 2010,1500 2010,1355 1970,1355 1970,1275 1965,1270 1950,1255 1945,1255 1915,1225 1915,1180
PGND on Top Layer "Top Layer-No Net 5" (solid, remove dead copper, pour order 12): 825,935 865,935 880,950 880,995 885,1000 885.98,1000.98 885.98,1060.99 954.01,1060.99 955,1060 955,1000 955,995 950,990 930,990 915,975 910,970 905,965 900,960 895,955 895,950 895,920 890,915 825,915 825,935
VIN on Top Layer "Top Layer-No Net 6" (solid, remove dead copper, pour order 14): 975,1097.32 977.32,1095 1210,1095 1210,965 1065,965 1060,965 1005,1020 1000,1020 975,1020 975,1135 1210,1135 1043.01,1085.26
VO on Top Layer "Top Layer-No Net 7" (solid, remove dead copper, pour order 17): 1930,1165 2040,1165 2090,1165 2185,1260 2300,1260 2340,1300 2850,1300 2900,1300 2970,1370 3250,1370 3250,1080 2850,1080 2075,1080 2050,1105 2045,1110 1965,1110 1960,1115 1930,1115
PGND on Top Layer "Top Layer-No Net 8" (solid, remove dead copper, pour order 19): 50,1040 350,1040 780,1040 780,790 885,790 925,750 980,750 980,826.99 989,835.99 1058.01,905 1060,905 1060,930 1320,930 1635,930 1635.88,930 1674.5,968.62 1680,974.12 1680,975 1680,985 1770,985 1780,985 1810,1015 1970,1015 2035,1015 2032.27,1017.73 2032.27,1040.02 2440.02,1040.02 2450,1050 3250,1050 3250,50 2850,50 50,50 50,1040
PGND on Top Layer "Bottom Layer-No Net" (solid, remove dead copper, pour order 21): 1835,1115 1915,1115 1915,1090.31 1915.35,1089.96 1920.31,1085 2025,1085 2025,1060 2045,1040 2045,997.64 2042.36,995 2042.36,985 1765,985 1795.49,1015.49 1857.03,1015.49 1857.03,1087.35 1854.42,1089.96 1834.65,1089.96 1834.65,1114.65 1835,1115
PGND on Bottom Layer "Bottom Layer-No Net 1" (solid, remove dead copper, pour order 23): 55,2350 3250,2350 3250,50 50,50 50,2350 55,2350

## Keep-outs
Keep-Out Layer:
  lines w10: 0,0 0,0 ; 0,0 3300,0 3300,2400 0,2400 0,0 ; 4434,3455 cw(c4434,3450) 4439,3450 ; 4434,3455 cw(c4434,3450) 4439,3450 ; 4434,3455 cw(c4434,3450) 4439,3450 ; 4434,3455 cw(c4434,3450) 4439,3450 ; 4434,3455 cw(c4434,3450) 4439,3450 ; 4434,3455 cw(c4434,3450) 4439,3450
  text ".Layer_Name" at 61,-858.49 h30

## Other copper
Top Layer:
  text ".Layer_Name" at 61,-858.49 h30
Bottom Layer:
  text ".Layer_Name" at 61,-858.49 h30

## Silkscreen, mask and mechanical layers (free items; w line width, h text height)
Top Overlay:
  circle w10: c1845,1260 r5
  lines w10: 750,710 2365,710 2365,1670 2365,1685 1250,1685 750,1685 750,710
  text "ON" at 1790,1800 h40
  text "OFF" at 1550,1795 h40
  text "EN" at 1675,1795 h40
  text "VIN" at 35,1470 h40
  text "S+" at 3117,1381 h40
  text "VOUT" at 3121,1105 h40
  text "GND" at 3121,974 h40
  text "MODE" at 2530,945 h40
  text "GND" at 2530,845 h40
  text "S-" at 3122,780 h40
  text "GND" at 35,745 h40
  text "GND" at 1670,405 h40
  text "PMP9772" at 1430,205 h50
  text "TPS61088 reference design" at 1050,100 h50
  text ".Layer_Name" at 61,-858.49 h30
Bottom Overlay:
  text ".Layer_Name" at 61,-858.49 h30
Top Paste:
  text ".Layer_Name" at 61,-858.49 h30
Bottom Paste:
  text ".Layer_Name" at 61,-858.49 h30
Top Solder:
  text ".Layer_Name" at 61,-858.49 h30
  text ".Layer_Name" at 61,-858.49 h30
Bottom Solder:
  text ".Layer_Name" at 61,-858.49 h30
Drill Guide:
  text ".Layer_Name" at 61,-858.49 h30
M1 Board Outline:
  lines w10: -5,0 ccw(c0,0) 0,-5 ; -5,0 ccw(c0,0) 0,-5 ; -5,0 -5,2400 ; -5,2400 cw(c0,2400) 0,2405 ; -5,2400 cw(c0,2400) 0,2405 ; 0,-5 3300,-5 ; 0,2405 3300,2405 ; 3300,-5 ccw(c3300,0) 3305,0 ; 3300,-5 ccw(c3300,0) 3305,0 ; 3300,2405 cw(c3300,2400) 3305,2400 ; 3300,2405 cw(c3300,2400) 3305,2400 ; 3305,0 3305,2400
  text ".Layer_Name" at 61,-858.49 h30
M2 Board Dimensions:
  rectangle: -516.5,-285.5 -391.5,-160.5
  rectangle: -391.5,-410.5 -16.5,-285.5
  lines w7: -516.5,-285.5 483.5,-285.5 ; -391.5,-410.5 -391.5,-160.5 ; -266.5,-410.5 -266.5,-160.5 ; -16.5,-410.5 -16.5,-160.5 ; 233.5,-410.5 233.5,-160.5 ; -516.5,-410.5 483.5,-410.5 483.5,-160.5 -516.5,-160.5 -516.5,-410.5
  lines w10: -516.5,-475.5 -516.5,-455.5 ; -456.5,-485.5 -516.5,-465.5 ; -456.5,-445.5 -516.5,-465.5 ; -292.42,-465.5 -516.5,-465.5 ; -97,160 -77,100 ; -97,2340 -77,2400 ; -87,100 -67,100 ; -87,2400 -67,2400 ; -77,969.09 -77,100 ; -77,1530.91 -77,2400 ; -57,160 -77,100 ; -57,2340 -77,2400 ; 1,-105 1,-85 ; 60.99,-115.02 1,-95 ; 61.01,-75.02 1,-95 ; 259.41,-465.5 483.5,-465.5 ; 423.5,-485.5 483.5,-465.5 ; 423.5,-445.5 483.5,-465.5 ; 483.5,-475.5 483.5,-455.5 ; 1370.09,-95.41 1,-95 ; 1931.91,-95.59 3301,-96 ; 3240.99,-115.98 3301,-96 ; 3241.01,-75.98 3301,-96 ; 3301,-106 3301,-86
  text "2300 (mil)" at -41.01,979.09 h60 r90
  text "3300 (mil)" at 1380.07,-131.41 h60 r359.98
  text "1000 (mil)" at -282.42,-501.49 h60
  text ".Layer_Name" at 61,-858.49 h30
M3 3D STEP Top:
  text ".Layer_Name" at 61,-858.49 h30
M4 3D STEP Bottom:
  text ".Layer_Name" at 61,-858.49 h30
M5 Assembly Top:
  lines w10: -808,-930.17 5792,-930.17 ; -808,-726.83 5794,-726.83 ; -808,-523.5 -808,-1133.5 3197,-1133.5 5794,-1133.5 5794,-523.5 -807.5,-523.5 -807.5,-1133.5 768,-1133.5 ; 1657,-1133.5 1657,-523.5 ; 2924,-726.83 2924,-523.5 ; 3764,-726.83 3764,-523.5 ; 4386,-1140 4386,-937.17
  text "COMPONENTS MARKED 'DNP' SHOULD NOT BE POPULATED." at 637.5,-318.5 h30
  text "ASSEMBLY VARIANT:" at 637,-434 h30
  text ".VariantName" at 1673,-434 h30
  text "PCB VIEWED FROM TOP SIDE" at -744.5,-655.67 h30
  text "BOARD #:" at 1732,-655.67 h30
  text ".PRJ_Number" at 2277.5,-655.67 h30
  text "REV:" at 3122,-655.67 h30
  text ".PCB_Rev" at 3413.5,-655.67 h30
  text "SVN REV:" at 3960,-655.67 h30
  text ".VersionControl_RevNumber" at 4466,-655.67 h30
  text "IGNORE ->" at -744.5,-858.49 h30
  text "PLOT NAME =" at -744.5,-1064.34 h30
  text ".plot_File_Name" at 61,-1064.34 h30
  text "GENERATED    :" at 1734,-1064.34 h30
  text ".Print_Date" at 2603.5,-1064.34 h30
  text ".Print_Time" at 3332.5,-1064.34 h30
  text "TEXAS INSTRUMENTS" at 4597,-1064.34 h30
M6 Assembly Bottom:
  lines w10: -808.5,-727.33 5793.5,-727.33 ; -806.5,-930.67 5793.5,-930.67 ; 599.5,-1140.5 599.5,-937.67 ; 1221.5,-727.33 1221.5,-524 ; 2061.5,-727.33 2061.5,-524 ; 3328.5,-1134 3328.5,-524 ; 4217.5,-1134 5793,-1134 5793,-524 -808.5,-524 -808.5,-1134 1788.5,-1134 5793.5,-1134 5793.5,-524
  text "COMPONENTS MARKED 'DNP' SHOULD NOT BE POPULATED." at 5586,-318 h30
  text ".VariantName" at 4542,-434 h30
  text "ASSEMBLY VARIANT:" at 5581,-434 h30
  text ".VersionControl_RevNumber" at 519.5,-656.17 h30
  text "SVN REV:" at 1025.5,-656.17 h30
  text ".PCB_Rev" at 1572,-656.17 h30
  text "REV:" at 1863.5,-656.17 h30
  text ".PRJ_Number" at 2708,-656.17 h30
  text "BOARD #:" at 3253.5,-656.17 h30
  text "PCB VIEWED FROM BOTTOM SIDE" at 5730,-656.17 h30
  text "IGNORE ->" at 2031.85,-858.49 h30
  text "TEXAS INSTRUMENTS" at 388.5,-1064.84 h30
  text ".Print_Time" at 1653,-1064.84 h30
  text ".Print_Date" at 2382,-1064.84 h30
  text "GENERATED    :" at 3251.5,-1064.84 h30
  text ".plot_File_Name" at 4924.5,-1064.84 h30
  text "PLOT NAME =" at 5730,-1064.84 h30
M9 Title Sheet:
  drawing of 57 lines, arcs and shapes, not listed
  text "1" at 223.84,8036.5 h30
  text "2" at 2719.5,8036.5 h30
  text "3" at 5208.84,8036.5 h30
  text "4" at 7715.51,8036.5 h30
  text "5" at 10214.5,8036.5 h30
  text "6" at 12719.5,8036.5 h30
  text "A" at -932.5,6893.5 h30
  text "A" at 13867.5,6893.5 h30
  text "B" at -932.5,4513.5 h30
  text "B" at 13867.5,4513.5 h30
  text "C" at -932.5,2138.5 h30
  text "C" at 13867.5,2138.5 h30
  text "PROJECT TITLE:" at 10827.5,277.5 h30
  text ".PRJ_Title" at 10877.5,144.17 h30
  text "DESIGNED FOR:" at 10827.5,-23.5 h30
  text ".PRJ_Customer" at 10877.5,-163.5 h30
  text "D" at -932.5,-231.5 h30
  text "D" at 13867.5,-231.5 h30
  text "FILE NAME:" at 10827.5,-323.5 h30
  text ".PCB_File_Name_No_Path" at 10877.5,-443.5 h30
  text "Texas Instruments (TI) and/or its licensors do not warrant the accuracy or completeness of this specification" at 5858,-605.34 h30
  text "ENGINEER:" at 10827.5,-613.5 h30
  text "LAYOUT BY:" at 12332.5,-613.5 h30
  text "or any information contained therein. TI and/or its licensors do not warrant that this design will meet" at 5813.01,-718 h30
  text ".PRJ_Engineer" at 10877.5,-768.49 h30
  text ".PCB_Layout" at 12383,-768.49 h30
  text "the specifications, will be suitable for your application or fit for any particular purpose, or will operate in" at 5813.01,-830.67 h30
  text ".Layer_Name" at 61,-858.49 h30
  text "ALTIUM DESIGNER VERSION:" at 12332.5,-923.5 h30
  text "an implementation. TI and/or its licensors do not warrant that the design is production worthy. You should" at 5813.01,-943.33 h30
  text "completely validate and test your design implementation to confirm the system functionality for your application." at 5858,-1056 h30
  text ".print_Scale" at 10877.5,-1056.83 h30
  text ".Application_BuildNumber" at 12383,-1056.83 h30
  text "1" at 223.84,-1263.5 h30
  text "2" at 2719.5,-1263.5 h30
  text "3" at 5208.84,-1263.5 h30
  text "4" at 7715.51,-1263.5 h30
  text "5" at 10214.5,-1263.5 h30
  text "6" at 12719.5,-1263.5 h30
M10 Fab Notes:
  drawing of 212 lines, arcs and shapes, not listed
  text "DESIGN INFORMATION" at 11865.02,6810 h30
  text "(REFER ALSO ARRAY/PANEL PROFILING INFORMATION)" at 11503.46,6648.29 h30
  text "BOARD SIZE" at 10817.46,6644 h30
  text "3450MIL" at 11279.78,6516.18 h30
  text "X" at 11785.46,6516.18 h30
  text "4950MIL" at 12016.78,6516.18 h30
  text "Number of Layers :" at 11220.46,6319 h30
  text "4" at 12315.27,6309 h30
  text "MIN. TRACK WIDTH:" at 11220.46,6180 h30
  text "8" at 12316.7,6180 h30
  text "MIL" at 12471.46,6180 h30
  text "MIN. CLEARANCE:" at 11220.46,6048 h30
  text "8" at 12316.7,6048 h30
  text "MIL" at 12471.46,6048 h30
  text "MIN. VIA PAD SIZE:" at 11220.46,5916 h30
  text "24" at 12286.71,5916 h30
  text "MIL" at 12471.46,5916 h30
  text "0.05mm (2MIL)" at 11915.46,5774.29 h30
  text "MINIMUM ANNULAR RING" at 10891.23,5770 h30
  text "EXTERNAL" at 12623.46,5770 h30
  text "PER" at 11091.23,5652 h30
  text "IPC-D-275 CLASS 2 LEVEL C" at 11311.23,5652 h30
  text "MIL, HOLES" at 12799.46,5539.71 h30
  text "+/-" at 12407,5539 h30
  text "+/-" at 13261,5539 h30
  text "REGISTRATION TOLERANCES:" at 10891.23,5534 h30
  text "METAL" at 12091,5534 h30
  text "5" at 12667.2,5534 h30
  text "3" at 13500.2,5534 h30
  text "MIL" at 13616.46,5534 h30
  text "MATERIAL:" at 10816.46,5324.54 h30
  text "FR-4 High Tg" at 11802.9,5184.21 h30
  text "FR-408" at 11237.46,5175.64 h30
  text "X" at 11649.46,5175.64 h30
  text "OTHER" at 12725.46,5175.64 h30
  text "62 MIL (1.6mm) +/-10%" at 11557.56,5012.92 h30
  text "THICKNESS:" at 10891.23,5008.64 h30
  text "X" at 11429.4,5008.64 h30
  text "OTHER" at 12842.46,5008.64 h30
  text "TOLERANCE:" at 10891.23,4850.64 h30
  text "X" at 11730.53,4850.64 h30
  text "ANSI IPC-6012 TYPE 3 CLASS 2" at 11917.47,4850.64 h30
  text "OTHER +/-" at 11917.46,4694.64 h30
  text "BOW & TWIST:" at 10891.23,4537.64 h30
  text "X" at 11730.53,4537.64 h30
  text "ANSI IPC-6012 TYPE 3 CLASS 2" at 11917.47,4537.64 h30
  text "OTHER +/-" at 11917.46,4379.13 h30
  text "COPPER THICKNESS (FINISHED):" at 10816.46,4243.64 h30
  text "1.4MIL (1oz)" at 11696.46,4090.92 h30
  text "2MIL (1.4oz)" at 12463.46,4090.92 h30
  text "2.8MIL (2oz)" at 13190.46,4090.92 h30
  text "X" at 13070,4089 h30
  text "OUTER:" at 11173.46,4086.64 h30
  text "1.4MIL (1oz)" at 11696.46,3933.92 h30
  text "2.8MIL (2oz)" at 12463.46,3933.92 h30
  text "N/A" at 13190,3934.29 h30
  text "INNER SIGNAL:" at 10884.38,3929.64 h30
  text "X" at 11569.42,3929.64 h30
  text "DRILLING:" at 10816.46,3790.64 h30
  text "REFERENCE:" at 10891.23,3673.64 h30
  text "X" at 11539.46,3673.64 h30
  text "AS SHOWN" at 11726.46,3673.64 h30
  text "X" at 12440.46,3673.64 h30
  text "NC_DRILL FILES" at 12577.46,3673.64 h30
  text "PTH MIN COPPER THICKNESS:" at 10891.23,3515.64 h30
  text "X" at 12241.46,3515.64 h30
  text "1MIL" at 12378.46,3515.64 h30
  text "OTHER" at 12875.46,3515.64 h30
  text "BOARD FINISH:" at 10816.46,3356.64 h30
  text "SILKSCREEN:" at 10971.68,3238.64 h30
  text "X" at 11920.46,3238.64 h30
  text "TOP" at 12046.46,3238.64 h30
  text "X" at 12430.46,3238.64 h30
  text "BOTTOM" at 12557.46,3238.64 h30
  text "SILKSCREEN COLOR:" at 10971.68,3071.64 h30
  text "X" at 11919.42,3071.64 h30
  text "WHITE" at 12046.46,3071.64 h30
  text "OTHER" at 12557.46,3071.64 h30
  text "SOLDER RESIST COLOR:" at 10971.68,2901.64 h30
  text "X" at 11539.42,2742.44 h30
  text "GREEN" at 11666.46,2742.44 h30
  text "BLUE" at 12257.46,2742.44 h30
  text "OTHER" at 12795.46,2742.44 h30
  text "IMMERSION GOLD (ENIG)" at 11877.46,2553.92 h30
  text "ENEPIG" at 13215,2550.64 h30
  text "SURFACE FINISH:" at 10816.46,2549.64 h30
  text "X" at 11690.51,2549.64 h30
  text "IMM. TIN/SILVER OR EQUIV" at 11146,2392.64 h30
  text "OTHER" at 12577.46,2392.64 h30
  text "ARRAY/PANEL:" at 10816.46,2213.64 h30
  text "CUT AND TRIM PER MECH LAYER 1" at 11877.46,2209.35 h30
  text "N.C. ROUTE" at 11877.46,2057.64 h30
  text "X" at 12556.46,2057.64 h30
  text "V. SCORE" at 12743.46,2057.64 h30
  text "CERTIFICATION:" at 10816.46,1920.64 h30
  text "MATERIALS AND WORKMANSHIP FOR ALL PCBS" at 11541.46,1920.64 h30
  text "TO MEET OR EXCEED THE REQUIREMENTS OF:" at 11541.46,1822.64 h30
  text "X" at 11167.96,1686.13 h30
  text "ANSI IPC-A-600F CLASS ->" at 11306.96,1686.13 h30
  text "X" at 12946.02,1686.13 h30
  text "2" at 13064.96,1686.14 h30
  text "1" at 12749.96,1684.64 h30
  text "3" at 13418.96,1684.64 h30
  text "X" at 11170.02,1526.64 h30
  text "UL 94V-0" at 11306.96,1526.64 h30
  text "X" at 11982.02,1526.64 h30
  text "RoHS" at 12118.96,1526.64 h30
  text "OTHER" at 12763.36,1526.64 h30
  text "PER ORDER" at 13160.42,1526.64 h30
  text "ADDITIONAL REQUIREMENTS:" at 10816.46,1385.64 h30
  text "MICROSECTION:" at 10891.23,1270.64 h30
  text "YES" at 11796.96,1270.64 h30
  text "REQUIRED" at 12658.46,1114.49 h30
  text "BARE BOARD ELEC. TEST:" at 10891.23,1111.64 h30
  text "NONE" at 12196.96,1111.64 h30
  text "PER ORDER" at 13250.46,1111.64 h30
  text "MANUFACTURER'S UL:" at 10891.23,954.64 h30
  text "RAIL" at 12056.96,950.35 h30
  text "METAL" at 12548.77,950.35 h30
  text "SILK" at 13060.46,950.35 h30
  text ".Layer_Name" at 61,-858.49 h30
M11 Gerber Information:
  lines w10: -808,-930.17 5792,-930.17 ; -808,-726.83 5794,-726.83 ; -808,-523.5 -808,-1133.5 3197,-1133.5 5794,-1133.5 5794,-523.5 -807.5,-523.5 -807.5,-1133.5 768,-1133.5 ; 1657,-1133.5 1657,-523.5 ; 2924,-726.83 2924,-523.5 ; 3764,-726.83 3764,-523.5 ; 4386,-1140 4386,-937.17
  text "ALL ARTWORK VIEWED FROM TOP SIDE" at -744.5,-655.67 h30
  text "BOARD #:" at 1732,-655.67 h30
  text ".PRJ_Number" at 2277.5,-655.67 h30
  text "REV:" at 3122,-655.67 h30
  text ".PCB_Rev" at 3413.5,-655.67 h30
  text "SVN REV:" at 3960,-655.67 h30
  text ".VersionControl_RevNumber" at 4466,-655.67 h30
  text "LAYER NAME =" at -744.5,-858.49 h30
  text "PLOT NAME =" at -744.5,-1064.34 h30
  text ".plot_File_Name" at 61,-1064.34 h30
  text "GENERATED    :" at 1734,-1064.34 h30
  text ".Print_Date" at 2603.5,-1064.34 h30
  text ".Print_Time" at 3332.5,-1064.34 h30
  text "TEXAS INSTRUMENTS" at 4597,-1064.34 h30
M12 Stackup:
  lines w1: 9639.04,7518.1 9959.04,7518.1 ; 9639.04,7535.5 9959.04,7535.5 ; 9579.04,7208.6 ccw(c9585.04,7208.6) 9585.04,7202.6 10013.04,7202.6 ccw(c10013.04,7208.6) 10019.04,7208.6 10019.04,7616.6 ccw(c10013.04,7616.6) 10013.04,7622.6 9585.04,7622.6 ccw(c9585.04,7616.6) 9579.04,7616.6 9579.04,7208.6
  lines w6: 10844,7460 13394,7460 ; 10844,7564.4 13394,7564.4 ; 10784,6975 ccw(c10818,6975) 10818,6941 13420,6941 ccw(c13420,6975) 13454,6975 13454,7681 ccw(c13420,7681) 13420,7715 10818,7715 ccw(c10818,7681) 10784,7681 10784,6975
  text "The Stackup Legend below this is static." at 11089.5,7874.5 h30
  text "If you change the stackup, update the Legend." at 11099.5,7784.5 h30
  text "Layer Stack Up Detail for: Ref_Design.PcbDoc" at 10844,7597.1 h30
  text "Layer Stack Up Detail for: TPS61088EngineeringEVM.PcbDoc" at 9639.04,7574.75 h30
  text "Layer" at 9639.04,7529 h30
  text "Gerber" at 9753.68,7529 h30
  text "Copper" at 9808.2,7529 h30
  text "Dielectric" at 9869.25,7529 h30
  text "Layer" at 10844,7525.4 h30
  text "Gerber" at 11739.81,7525.4 h30
  text "Copper" at 12303.33,7525.4 h30
  text "Dielectric" at 12906.04,7525.4 h30
  text "Name" at 9639.04,7521 h30
  text "Document" at 9753.68,7521 h30
  text "Thickness" at 9808.2,7521 h30
  text "Material" at 9869.25,7521 h30
  text "Top Solder Mask" at 9639.04,7495.73 h30
  text "(.GTS)" at 9753.68,7495.73 h30
  text "Solder Resist" at 9869.25,7495.73 h30
  text "Name" at 10844,7477.4 h30
  text "Document" at 11739.81,7477.4 h30
  text "Thickness" at 12303.33,7477.4 h30
  text "Material" at 12906.04,7477.4 h30
  text "Top Layer" at 9639.04,7451.98 h30
  text "(.GTL)" at 9753.68,7451.98 h30
  text "2.8mil" at 9808.2,7451.98 h30 r9.84
  text "FR-4" at 9869.25,7430.1 h30
  text "MidLayer1" at 9639.04,7408.23 h30
  text "(.G1)" at 9753.68,7408.23 h30
  text "1.4mil" at 9808.2,7408.23 h30
  text "FR-4" at 9869.25,7386.35 h30
  text "Top Solder Mask" at 10844,7384.44 h30
  text "(.GTS)" at 11739.81,7384.44 h30
  text "Solder Resist" at 12906.04,7384.44 h30
  text "MidLayer2" at 9639.04,7364.48 h30
  text "(.G2)" at 9753.68,7364.48 h30
  text "1.4mil" at 9808.2,7364.48 h30
  text "FR-4" at 9869.25,7342.6 h30
  text "Bottom Layer" at 9639.04,7320.73 h30
  text "(.GBL)" at 9753.68,7320.73 h30
  text "2.8mil" at 9808.2,7320.73 h30
  text "Top Layer" at 10844,7287.69 h30
  text "(.GTL)" at 11739.81,7287.69 h30
  text "1.4mil" at 12303.33,7287.69 h30
  text "Bottom Solder Mask" at 9639.04,7276.98 h30
  text "(.GBS)" at 9753.68,7276.98 h30
  text "Solder Resist" at 9869.25,7276.98 h30
  text "FR-4" at 12906.04,7239.31 h30
  text "Bottom Layer" at 10844,7190.94 h30
  text "(.GBL)" at 11739.81,7190.94 h30
  text "1.4mil" at 12303.33,7190.94 h30
  text "Bottom Solder Mask" at 10844,7094.19 h30
  text "(.GBS)" at 11739.81,7094.19 h30
  text "Solder Resist" at 12906.04,7094.19 h30
  text ".Layer_Name" at 61,-858.49 h30
M13 Component Bodies Top:
  text ".Layer_Name" at 61,-858.49 h30
M14 Component Bodies Bottom:
  text ".Layer_Name" at 61,-858.49 h30
M15 Courtyards Top:
  text ".Layer_Name" at 61,-858.49 h30
M16 Courtyards Bottom:
  text ".Layer_Name" at 61,-858.49 h30
Drill Drawing:
  lines w10: 4248.12,1155 4298.12,1155 4273.12,1105 4248.12,1155 ; 4248.12,1255 4298.12,1255 4298.12,1305 4248.12,1305 4248.12,1255 ; 4248.12,1417.5 4260.62,1417.5 4273.12,1405 4285.62,1417.5 4298.12,1417.5 4285.62,1430 4298.12,1442.5 4285.62,1442.5 4273.12,1455 4260.62,1442.5 4248.12,1442.5 4260.62,1430 4248.12,1417.5 ; 4248.12,1567.5 4260.62,1567.5 4260.62,1555 4285.62,1555 4285.62,1567.5 4298.12,1567.5 4298.12,1592.5 4285.62,1592.5 4285.62,1605 4260.62,1605 4260.62,1592.5 4248.12,1592.5 4248.12,1567.5 ; 4248.12,1705 4273.12,1717.5 4298.12,1705 4285.62,1730 4298.12,1755 4273.12,1742.5 4248.12,1755 4260.62,1730 4248.12,1705 ; 4248.12,1855 4248.12,1867.5 4260.62,1880 4248.12,1892.5 4248.12,1905 4260.62,1905 4273.12,1892.5 4285.62,1905 4298.12,1905 4298.12,1892.5 4285.62,1880 4298.12,1867.5 4298.12,1855 4285.62,1855 4273.12,1867.5 4260.62,1855 4248.12,1855
  lines w15: 4180,1060 8058.97,1060 ; 4180,1960 8058.97,1960 ; 4730.88,910 4730.88,2110 ; 5428.69,910 5428.69,2110 ; 6774.29,910 6774.29,2110 ; 7280.17,910 7280.17,2110 ; 4180,910 8058.97,910 8058.97,2110 4180,2110 4180,910
  text "Symbol" at 4270,2005 h72
  text "Hit Count" at 4775.88,2005 h72
  text "Finished Hole Size" at 5473.69,2005 h72
  text "Plated" at 6819.29,2005 h72
  text "Hole Type" at 7325.17,2005 h72
  text "4" at 4775.88,1855 h60
  text "125.98mil (3.200mm)" at 5473.69,1855 h60
  text "PTH" at 6819.29,1855 h60
  text "Round" at 7325.17,1855 h60
  text "6" at 4775.88,1705 h60
  text "50.00mil (1.270mm)" at 5473.69,1705 h60
  text "PTH" at 6819.29,1705 h60
  text "Round" at 7325.17,1705 h60
  text "6" at 4775.88,1555 h60
  text "63.00mil (1.600mm)" at 5473.69,1555 h60
  text "PTH" at 6819.29,1555 h60
  text "Round" at 7325.17,1555 h60
  text "9" at 4775.88,1405 h60
  text "40.00mil (1.016mm)" at 5473.69,1405 h60
  text "PTH" at 6819.29,1405 h60
  text "Round" at 7325.17,1405 h60
  text "16" at 4775.88,1255 h60
  text "7.87mil (0.200mm)" at 5473.69,1255 h60
  text "PTH" at 6819.29,1255 h60
  text "Round" at 7325.17,1255 h60
  text "245" at 4775.88,1105 h60
  text "10.00mil (0.254mm)" at 5473.69,1105 h60
  text "PTH" at 6819.29,1105 h60
  text "Round" at 7325.17,1105 h60
  text "286 Total" at 4775.88,955 h60
  text ".Layer_Name" at 61,-858.49 h30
